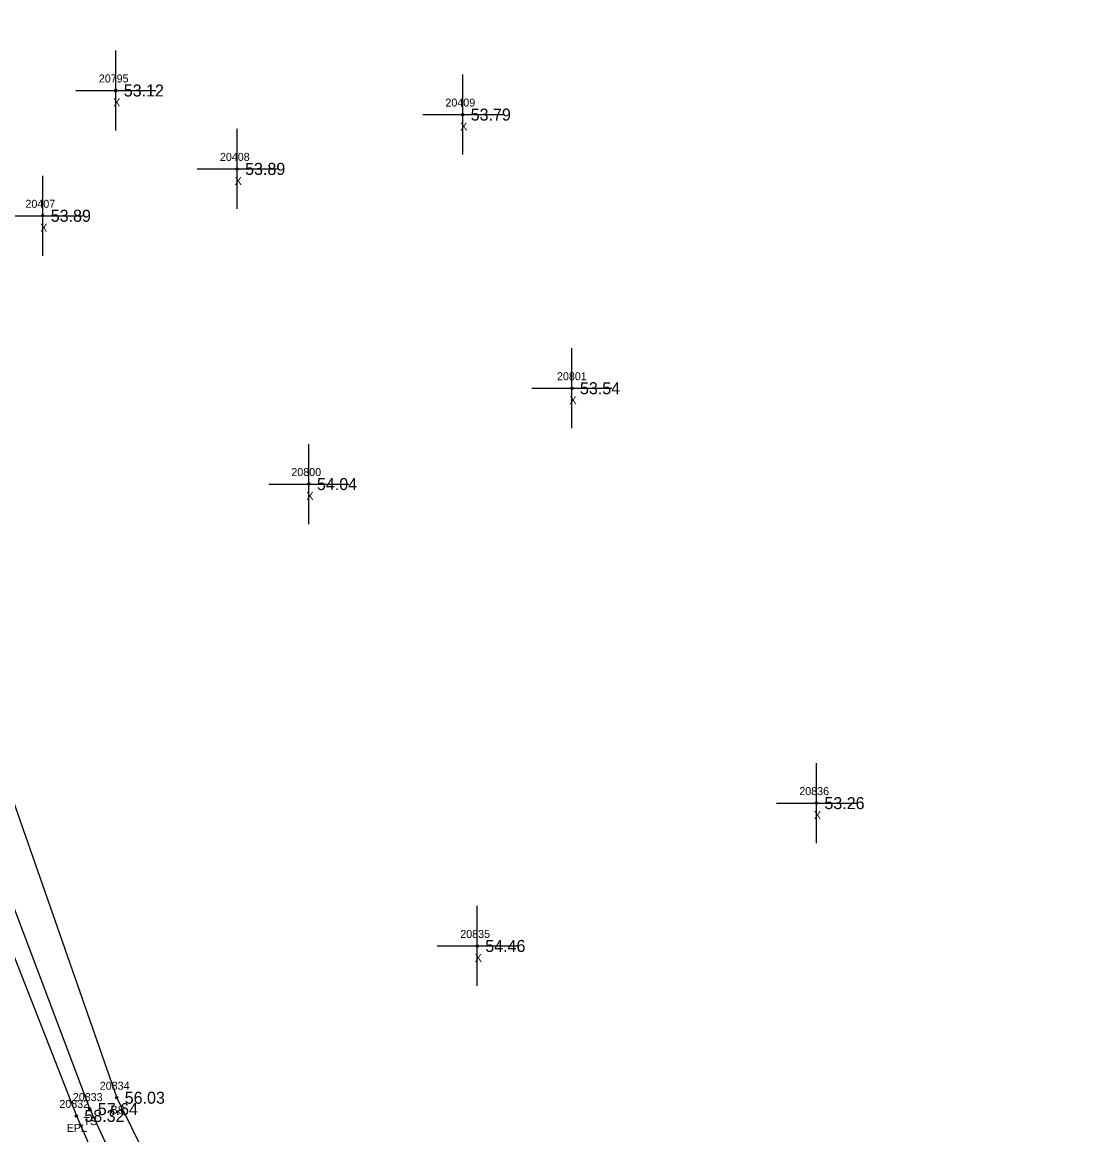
# Model space of a CAD drawing. Extents: x 2396547 to 2397655, y 770185 to 772649.
# Drawn here: x 2397147.4 to 2397280.8, y 771116.1 to 771255.2 of the extents above; entities that cross this region are included whole.
import ezdxf

# ---------------------------------------------------------------- set-up
doc = ezdxf.new("R2010")
doc.units = 0
for name, color, linetype in [('RD_DTM_BkLn2', 7, 'Continuous'), ('RD_DTM_BkLn_txCode', 7, 'Continuous'), ('RD_EX_Misc', 7, 'Continuous'), ('RD_EX_Misc_txCode', 7, 'Continuous'), ('RD_EX_Road', 7, 'Continuous'), ('RD_EX_Road_txCode', 7, 'Continuous'), ('RD_EX_TX_Misc_ELEV', 7, 'Continuous'), ('RD_EX_TX_Road_ELEV', 7, 'Continuous'), ('RD_SMD_Locator', 7, 'Continuous')]:
    doc.layers.add(name, color=color, linetype=linetype)

msp = doc.modelspace()

# ---------------------------------------------------------------- linework, layer by layer
at = {"layer": 'RD_DTM_BkLn2'}
for points in [[(2397076.78, 771367.04), (2397097.18, 771355.59), (2397095.19, 771340.51), (2397107.46, 771294.95), (2397125.86, 771232.19), (2397125.86, 771232.19), (2397138.17, 771181.02), (2397159.24, 771120.76), (2397175.38, 771088.12), (2397179.45, 771097.49), (2397196.45, 771092.84), (2397253.33, 771096.54)], [(2397076.87, 771363.73), (2397092.63, 771353.52), (2397090.96, 771344.27), (2397084.99, 771338.48), (2397096.6, 771290.87), (2397116.69, 771229.78), (2397116.69, 771229.78), (2397133.23, 771179.22), (2397155.87, 771119.34), (2397173.3, 771081.82), (2397181.13, 771084.07), (2397253.33, 771087)]]:
    msp.add_lwpolyline(points, dxfattribs=at)
at = {"layer": 'RD_EX_Misc'}
for p, q in [((2397159.12, 771241.65), (2397159.12, 771251.65)), ((2397202.49, 771238.64), (2397202.49, 771248.64)), ((2397154.12, 771246.65), (2397164.12, 771246.65)), ((2397197.49, 771243.64), (2397207.49, 771243.64)), ((2397174.29, 771231.85), (2397174.29, 771241.85)), ((2397169.29, 771236.85), (2397179.29, 771236.85)), ((2397149.99, 771225.99), (2397149.99, 771235.99)), ((2397144.99, 771230.99), (2397154.99, 771230.99)), ((2397216.15, 771204.44), (2397216.15, 771214.44)), ((2397211.15, 771209.44), (2397221.15, 771209.44)), ((2397183.27, 771192.46), (2397183.27, 771202.46)), ((2397178.27, 771197.46), (2397188.27, 771197.46)), ((2397246.71, 771152.58), (2397246.71, 771162.58)), ((2397241.71, 771157.58), (2397251.71, 771157.58)), ((2397204.31, 771134.73), (2397204.31, 771144.73)), ((2397199.31, 771139.73), (2397209.31, 771139.73))]:
    msp.add_line(p, q, dxfattribs=at)
at = {"layer": 'RD_EX_Road'}
msp.add_lwpolyline([(2397113.76, 771228.75), (2397130.87, 771177.98), (2397154.19, 771118.49), (2397170.38, 771081.25), (2397178.53, 771063.49), (2397207.96, 771004.56), (2397238.54, 770949.11), (2397245.72, 770936.59), (2397280.76, 770876.73)], dxfattribs=at)
at = {"layer": 'RD_SMD_Locator'}
for centre in [(2397159.12, 771246.65), (2397202.49, 771243.64), (2397174.29, 771236.85), (2397149.99, 771230.99), (2397216.15, 771209.44), (2397183.27, 771197.46), (2397246.71, 771157.58), (2397204.31, 771139.73), (2397159.24, 771120.76), (2397154.19, 771118.49), (2397155.87, 771119.34)]:
    msp.add_circle(centre, 0.15, dxfattribs=at)

# ---------------------------------------------------------------- texts
at = {"layer": 'RD_DTM_BkLn_txCode'}
for s, p in [('20834', (2397157.12, 771121.76)), ('20833', (2397153.75, 771120.34)), ('BS', (2397158.46, 771118.76)), ('TS', (2397155.08, 771117.34))]:
    msp.add_text(s, height=1, dxfattribs=at).set_placement(p)
at = {"layer": 'RD_EX_Misc_txCode'}
for s, p in [('20795', (2397157, 771247.65)), ('X', (2397158.8, 771244.65)), ('20409', (2397200.33, 771244.64)), ('X', (2397202.17, 771241.64)), ('20408', (2397172.14, 771237.85)), ('X', (2397173.98, 771234.85)), ('20407', (2397147.83, 771231.99)), ('X', (2397149.67, 771228.99)), ('20801', (2397214.28, 771210.44)), ('X', (2397215.84, 771207.44)), ('20800', (2397181.07, 771198.46)), ('X', (2397182.95, 771195.46)), ('20836', (2397244.57, 771158.58)), ('X', (2397246.39, 771155.58)), ('20835', (2397202.19, 771140.73)), ('X', (2397203.99, 771137.73))]:
    msp.add_text(s, height=1, dxfattribs=at).set_placement(p)
at = {"layer": 'RD_EX_Road_txCode'}
for s, p in [('20832', (2397152.07, 771119.49)), ('EPL', (2397152.98, 771116.49))]:
    msp.add_text(s, height=1, dxfattribs=at).set_placement(p)
at = {"layer": 'RD_EX_TX_Misc_ELEV'}
for s, p in [('53.12', (2397160.12, 771245.9)), ('53.79', (2397203.49, 771242.89)), ('53.89', (2397175.29, 771236.1)), ('53.89', (2397150.99, 771230.24)), ('53.54', (2397217.15, 771208.69)), ('54.04', (2397184.27, 771196.71)), ('53.26', (2397247.71, 771156.83)), ('54.46', (2397205.31, 771138.98)), ('56.03', (2397160.24, 771120.01)), ('57.64', (2397156.87, 771118.59))]:
    msp.add_text(s, height=1.5, dxfattribs=at).set_placement(p)
at = {"layer": 'RD_EX_TX_Road_ELEV'}
msp.add_text('58.32', height=1.5, dxfattribs=at).set_placement((2397155.19, 771117.74))

doc.saveas('drawing.dxf')
